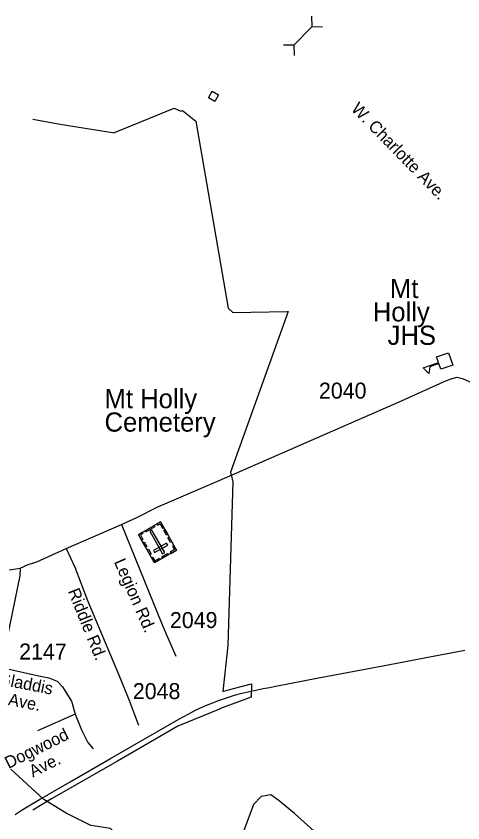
# Model space of a CAD drawing. Extents: x 1364363 to 1407445, y 538563 to 573342.
# Drawn here: x 1392969 to 1396463, y 565438 to 571741 of the extents above; entities that cross this region are included whole.
import ezdxf

# ---------------------------------------------------------------- set-up
doc = ezdxf.new("R2010")
doc.units = 0
for name, color, linetype in [('Default', 7, 'Continuous'), ('Exist Boundary Political City Limit New', 7, 'Continuous'), ('Exist Cultural Cemetery CELL', 7, 'Continuous'), ('Exist Cultural Cemetery Label', 7, 'Continuous'), ('Exist Cultural Educational Facility High CELL', 7, 'Continuous'), ('Exist Cultural Educational Facility High Label', 7, 'Continuous'), ('Exist Hydrographic Creek Single Shore', 7, 'Continuous'), ('Exist Railroad Mainline', 7, 'Continuous'), ('Exist Road Primary NC Label', 7, 'Continuous'), ('Exist Road Primary NC Structure Culvert CELL', 7, 'Continuous'), ('Exist Road Secondary Type 51 Attributed', 7, 'Continuous'), ('Exist Road Secondary Type 51 Label', 7, 'Continuous'), ('Exist Road Secondary Type 51 Number Label', 7, 'Continuous')]:
    doc.layers.add(name, color=color, linetype=linetype)

msp = doc.modelspace()

# ---------------------------------------------------------------- linework, layer by layer
at = {"layer": 'Default'}
msp.add_lwpolyline([(1394473.6, 571102.8), (1394503.4, 571155), (1394552.9, 571126.7), (1394523.1, 571074.5)], close=True, dxfattribs=at)
msp.add_lwpolyline([(1394473.6, 571102.8), (1394503.4, 571155), (1394552.9, 571126.7), (1394523.1, 571074.5)], close=True, dxfattribs=at)
at = {"layer": 'Exist Boundary Political City Limit New'}
msp.add_lwpolyline([(1393099.7, 570935.8), (1393314.2, 570895.9), (1393737.4, 570830.1), (1393738.4, 570830.8), (1394204.2, 571022.7), (1394257, 570998.2), (1394270.8, 571003.4), (1394375, 570920.7), (1394628.5, 569458.8), (1394664.9, 569424.3), (1395089.4, 569433.2), (1395095.6, 569431.9), (1394645.5, 568178.2), (1394664.6, 568103.6), (1394623.6, 566822.8), (1394586.2, 566464.2), (1394658.9, 566486.1), (1394808.9, 566523.2), (1394806.6, 566421.3), (1394560.6, 566328.9), (1394561, 566326.6), (1394235, 566193.5), (1393761.6, 565920.6), (1393246, 565625.8), (1393099.7, 565536.2)], dxfattribs=at)
at = {"layer": 'Exist Cultural Cemetery CELL'}
for points in [[(1394224.1, 567568.6), (1394050.9, 567470.5), (1393925.3, 567692), (1394098.5, 567790.1)], [(1394224.1, 567568.6), (1394050.9, 567470.5), (1393925.3, 567692), (1394098.5, 567790.1)], [(1394069.8, 567773.8), (1394075.4, 567763.8), (1394094.6, 567774.7), (1394114.5, 567739.5), (1394124.2, 567745), (1394098.6, 567790.1)], [(1394069.8, 567773.8), (1394075.4, 567763.8), (1394094.6, 567774.7), (1394114.5, 567739.5), (1394124.2, 567745), (1394098.6, 567790.1)], [(1394054.2, 567751.8), (1393980.4, 567710), (1393974.7, 567719.9), (1394048.6, 567761.8)], [(1394054.2, 567751.8), (1393980.4, 567710), (1393974.7, 567719.9), (1394048.6, 567761.8)], [(1394114.8, 567540.4), (1394131, 567549.6), (1394031, 567726), (1394014.8, 567716.8)], [(1394114.8, 567540.4), (1394131, 567549.6), (1394031, 567726), (1394014.8, 567716.8)], [(1394133, 567729.3), (1394154.4, 567691.6), (1394144.5, 567686), (1394123.1, 567723.7)], [(1394133, 567729.3), (1394154.4, 567691.6), (1394144.5, 567686), (1394123.1, 567723.7)], [(1393954.1, 567708.3), (1393959.8, 567698.3), (1393940.7, 567687.5), (1393960.6, 567652.3), (1393950.9, 567646.8), (1393925.3, 567692)], [(1393954.1, 567708.3), (1393959.8, 567698.3), (1393940.7, 567687.5), (1393960.6, 567652.3), (1393950.9, 567646.8), (1393925.3, 567692)], [(1394166.2, 567670.8), (1394187.5, 567633.2), (1394177.6, 567627.5), (1394156.3, 567665.2)], [(1394166.2, 567670.8), (1394187.5, 567633.2), (1394177.6, 567627.5), (1394156.3, 567665.2)], [(1393970.8, 567634.7), (1393992.2, 567597.1), (1393982.3, 567591.4), (1393960.9, 567629.1)], [(1393970.8, 567634.7), (1393992.2, 567597.1), (1393982.3, 567591.4), (1393960.9, 567629.1)], [(1394155, 567607.7), (1394145.8, 567624), (1394043.4, 567565.9), (1394052.6, 567549.7)], [(1394155, 567607.7), (1394145.8, 567624), (1394043.4, 567565.9), (1394052.6, 567549.7)], [(1394202.7, 567606.3), (1394192.8, 567600.7), (1394208.7, 567572.7), (1394173.4, 567552.7), (1394178.9, 567543), (1394224.1, 567568.6)], [(1394202.7, 567606.3), (1394192.8, 567600.7), (1394208.7, 567572.7), (1394173.4, 567552.7), (1394178.9, 567543), (1394224.1, 567568.6)], [(1394003.3, 567577.4), (1394024.7, 567539.7), (1394014.8, 567534.1), (1393993.4, 567571.8)], [(1394003.3, 567577.4), (1394024.7, 567539.7), (1394014.8, 567534.1), (1393993.4, 567571.8)], [(1394159.6, 567532.1), (1394114.5, 567506.6), (1394108.9, 567516.5), (1394154, 567542)], [(1394159.6, 567532.1), (1394114.5, 567506.6), (1394108.9, 567516.5), (1394154, 567542)], [(1394029.4, 567508.2), (1394039.3, 567513.8), (1394055.2, 567485.7), (1394090.4, 567505.8), (1394095.9, 567496.1), (1394050.8, 567470.5)], [(1394029.4, 567508.2), (1394039.3, 567513.8), (1394055.2, 567485.7), (1394090.4, 567505.8), (1394095.9, 567496.1), (1394050.8, 567470.5)]]:
    msp.add_lwpolyline(points, close=True, dxfattribs=at)
at = {"layer": 'Exist Cultural Educational Facility High CELL'}
msp.add_lwpolyline([(1396383.7, 569014.4), (1396291.2, 568982.4), (1396276.1, 569026), (1396205.2, 569001.4), (1396197.6, 568949.1), (1396151.5, 568993.1), (1396273, 569035), (1396258, 569078.5), (1396350.5, 569110.5)], close=True, dxfattribs=at)
msp.add_lwpolyline([(1396383.7, 569014.4), (1396291.2, 568982.4), (1396276.1, 569026), (1396205.2, 569001.4), (1396197.6, 568949.1), (1396151.5, 568993.1), (1396273, 569035), (1396258, 569078.5), (1396350.5, 569110.5)], close=True, dxfattribs=at)
at = {"layer": 'Exist Hydrographic Creek Single Shore'}
for points in [[(1396383, 564757.5), (1396211.6, 564800.4), (1396130.6, 564900.5), (1395824.7, 565064.2), (1395604.4, 565148.1), (1395472.2, 565222.8), (1395453.6, 565236.3), (1395145.1, 565512.7), (1395026.5, 565611.1), (1394962.1, 565656.9), (1394885.8, 565643.3), (1394824.8, 565582.3), (1394729.7, 565322.6), (1394504, 565194.4), (1394090.5, 565123.2), (1393863.7, 565183.5), (1393798.8, 565302.8), (1393707.2, 565395.2), (1393553.7, 565417.9), (1393360.4, 565514.6), (1393185.7, 565619.6), (1392928.3, 565859)], [(1396383, 564757.5), (1396211.6, 564800.4), (1396130.6, 564900.5), (1395824.7, 565064.2), (1395604.4, 565148.1), (1395472.2, 565222.8), (1395453.6, 565236.3), (1395145.1, 565512.7), (1395026.5, 565611.1), (1394962.1, 565656.9), (1394885.8, 565643.3), (1394824.8, 565582.3), (1394729.7, 565322.6), (1394504, 565194.4), (1394090.5, 565123.2), (1393863.7, 565183.5), (1393798.8, 565302.8), (1393707.2, 565395.2), (1393553.7, 565417.9), (1393360.4, 565514.6), (1393185.7, 565619.6), (1393099.7, 565699.6)]]:
    msp.add_lwpolyline(points, dxfattribs=at)
at = {"layer": 'Exist Railroad Mainline'}
for points in [[(1392960.7, 565502.6), (1393015.4, 565539.7), (1393093.6, 565587.1), (1393152.5, 565621.4), (1393216.2, 565658), (1393219.5, 565660), (1393392.3, 565759.2), (1393707.5, 565940.4), (1394241.1, 566248.3), (1394319.6, 566290.3), (1394373.2, 566318.4), (1394411.5, 566335.9), (1394458.3, 566356.9), (1394493.9, 566371.3), (1394551.6, 566395.5), (1394629.9, 566420.1), (1394668.7, 566432.7), (1394723.5, 566448.4), (1394770.1, 566460), (1394807.6, 566467), (1394900.5, 566487.4), (1394951.8, 566496.4), (1395000.4, 566505.5), (1395322, 566567.6), (1395796.3, 566658), (1396000.2, 566696.5), (1396176.9, 566730.1), (1396478.7, 566787.5)], [(1393099.7, 565590.6), (1393152.5, 565621.4), (1393216.2, 565658), (1393219.5, 565660), (1393392.3, 565759.2), (1393707.5, 565940.4), (1394241.1, 566248.3), (1394319.6, 566290.3), (1394373.2, 566318.4), (1394411.5, 566335.9), (1394458.3, 566356.9), (1394493.9, 566371.3), (1394551.6, 566395.5), (1394629.9, 566420.1), (1394668.7, 566432.7), (1394723.5, 566448.4), (1394770.1, 566460), (1394807.6, 566467), (1394900.5, 566487.4), (1394951.8, 566496.4), (1395000.4, 566505.5), (1395322, 566567.6), (1395796.3, 566658), (1396000.2, 566696.5), (1396176.9, 566730.1), (1396478.7, 566787.5)]]:
    msp.add_lwpolyline(points, dxfattribs=at)
at = {"layer": 'Exist Road Primary NC Structure Culvert CELL'}
for p, q in [((1395279.4, 571740.7), (1395282.3, 571657.5)), ((1395282.3, 571657.5), (1395143.1, 571516.1)), ((1395365.6, 571655.8), (1395282.3, 571657.5)), ((1395059.9, 571517.7), (1395143.1, 571516.1)), ((1395146, 571432.9), (1395143.1, 571516.1))]:
    msp.add_line(p, q, dxfattribs=at)
at = {"layer": 'Exist Road Secondary Type 51 Attributed'}
for p, q in [((1393361.4, 567582), (1393792.3, 567768.5)), ((1393361.4, 567582), (1393792.3, 567768.5)), ((1393431.8, 566288.5), (1393136.1, 566158.1)), ((1393431.8, 566288.5), (1393136.1, 566158.1))]:
    msp.add_line(p, q, dxfattribs=at)
for points in [[(1393792.3, 567768.5), (1393913.8, 567825.1), (1394077.6, 567907.4), (1394557.7, 568113.6), (1394717.7, 568183.6), (1395361.4, 568465.2), (1395958.8, 568724.2), (1396335.8, 568894.3), (1396378.6, 568910.9), (1396418.9, 568920.9), (1396460.9, 568908.5), (1396542, 568874.2)], [(1393792.3, 567768.5), (1393913.8, 567825.1), (1394077.6, 567907.4), (1394557.7, 568113.6), (1394717.7, 568183.6), (1395361.4, 568465.2), (1395958.8, 568724.2), (1396335.8, 568894.3), (1396378.6, 568910.9), (1396418.9, 568920.9), (1396460.9, 568908.5), (1396542, 568874.2)], [(1393792.3, 567768.5), (1394079.5, 567064.6), (1394143.1, 566912.7), (1394156.2, 566883.9), (1394219.1, 566741.3)], [(1393792.3, 567768.5), (1394079.5, 567064.6), (1394143.1, 566912.7), (1394156.2, 566883.9), (1394219.1, 566741.3)], [(1392999.6, 567429.3), (1393063.1, 567455.6), (1393130.8, 567477.7), (1393361.4, 567582)], [(1393099.7, 567467.5), (1393130.8, 567477.7), (1393361.4, 567582)], [(1393361.4, 567582), (1393429.1, 567436.2), (1393528.5, 567175.1), (1393770.2, 566600.4), (1393850.3, 566401.8), (1393926.1, 566202.6)], [(1393361.4, 567582), (1393429.1, 567436.2), (1393528.5, 567175.1), (1393770.2, 566600.4), (1393850.3, 566401.8), (1393926.1, 566202.6)], [(1392358.8, 567404.5), (1392756, 567409.3), (1392933.3, 567416.9), (1392999.6, 567429.3)], [(1392999.6, 567429.3), (1392998.2, 567367.2), (1392898.8, 566886.4), (1392840.9, 566655.8)], [(1392840.9, 566655.8), (1393133, 566589.4), (1393224.7, 566571.6), (1393290.1, 566545.6), (1393332.8, 566500.5), (1393403.2, 566388.8), (1393431.8, 566288.5)], [(1393099.7, 566597), (1393133, 566589.4), (1393224.7, 566571.6), (1393290.1, 566545.6), (1393332.8, 566500.5), (1393403.2, 566388.8), (1393431.8, 566288.5)], [(1393431.8, 566288.5), (1393479.5, 566164.1), (1393529.6, 566065.7), (1393571.1, 566015.9)], [(1393431.8, 566288.5), (1393479.5, 566164.1), (1393529.6, 566065.7), (1393571.1, 566015.9)]]:
    msp.add_lwpolyline(points, dxfattribs=at)

# ---------------------------------------------------------------- texts
at = {"layer": 'Exist Cultural Cemetery Label'}
for s, p in [('Mt Holly', (1393660.5, 568677.5)), ('Mt Holly', (1393660.5, 568677.5)), ('Cemetery', (1393660.5, 568494.7)), ('Cemetery', (1393660.5, 568494.7))]:
    msp.add_text(s, height=150, dxfattribs=at).set_placement(p)
at = {"layer": 'Exist Cultural Educational Facility High Label'}
for s, p in [('Mt ', (1395892.3, 569538.2)), ('Mt ', (1395892.3, 569538.2)), ('Holly ', (1395758.3, 569355.4)), ('Holly ', (1395758.3, 569355.4)), ('JHS', (1395874.2, 569172.6)), ('JHS', (1395874.2, 569172.6))]:
    msp.add_text(s, height=150, dxfattribs=at).set_placement(p)
at = {"layer": 'Exist Road Primary NC Label'}
msp.add_text('W. Charlotte Ave.', height=95, rotation=314.32364, dxfattribs=at).set_placement((1395583.2, 571010.2))
msp.add_text('W. Charlotte Ave.', height=95, rotation=314.32364, dxfattribs=at).set_placement((1395583.2, 571010.2))
at = {"layer": 'Exist Road Secondary Type 51 Label'}
for s, rotation, p in [('Legion Rd.', 293.64513, (1393732.3, 567478.2)), ('Legion Rd.', 293.64513, (1393732.3, 567478.2)), ('Riddle Rd.', 292.00866, (1393372, 567248.5)), ('Riddle Rd.', 292.00866, (1393372, 567248.5)), ('Gladdis', 349.01947, (1392823.8, 566521.3)), (' Ave.', 349.01947, (1392867.3, 566366)), ('Dogwood', 26.33309, (1392909.3, 565858.6)), ('    Ave.', 26.33309, (1392973.3, 565729.3))]:
    msp.add_text(s, height=95, rotation=rotation, dxfattribs=at).set_placement(p)
at = {"layer": 'Exist Road Secondary Type 51 Number Label'}
for s, p in [('2040', (1395337.4, 568752.5)), ('2040', (1395337.4, 568752.5)), ('2049', (1394172.1, 566960.1)), ('2049', (1394172.1, 566960.1)), ('2147', (1392993, 566714.4)), ('2048', (1393882, 566405)), ('2048', (1393882, 566405))]:
    msp.add_text(s, height=125, dxfattribs=at).set_placement(p)

doc.saveas('drawing.dxf')
